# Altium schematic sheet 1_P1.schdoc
size 431 x 309 mm; Symbol: Sheet-Symbol_A4; Device: Sheet-Symbol_A4; @Page Name: P1; @Create Date: 2023-05-28; @Page Count: 1; @Page No: 1; @Project Name: esp32s3_tpkb; @Schematic Name: Schematic1; @Update Date: 2023-06-06; Company: 嘉立创EDA; Page Size: A4; Version: V1.0
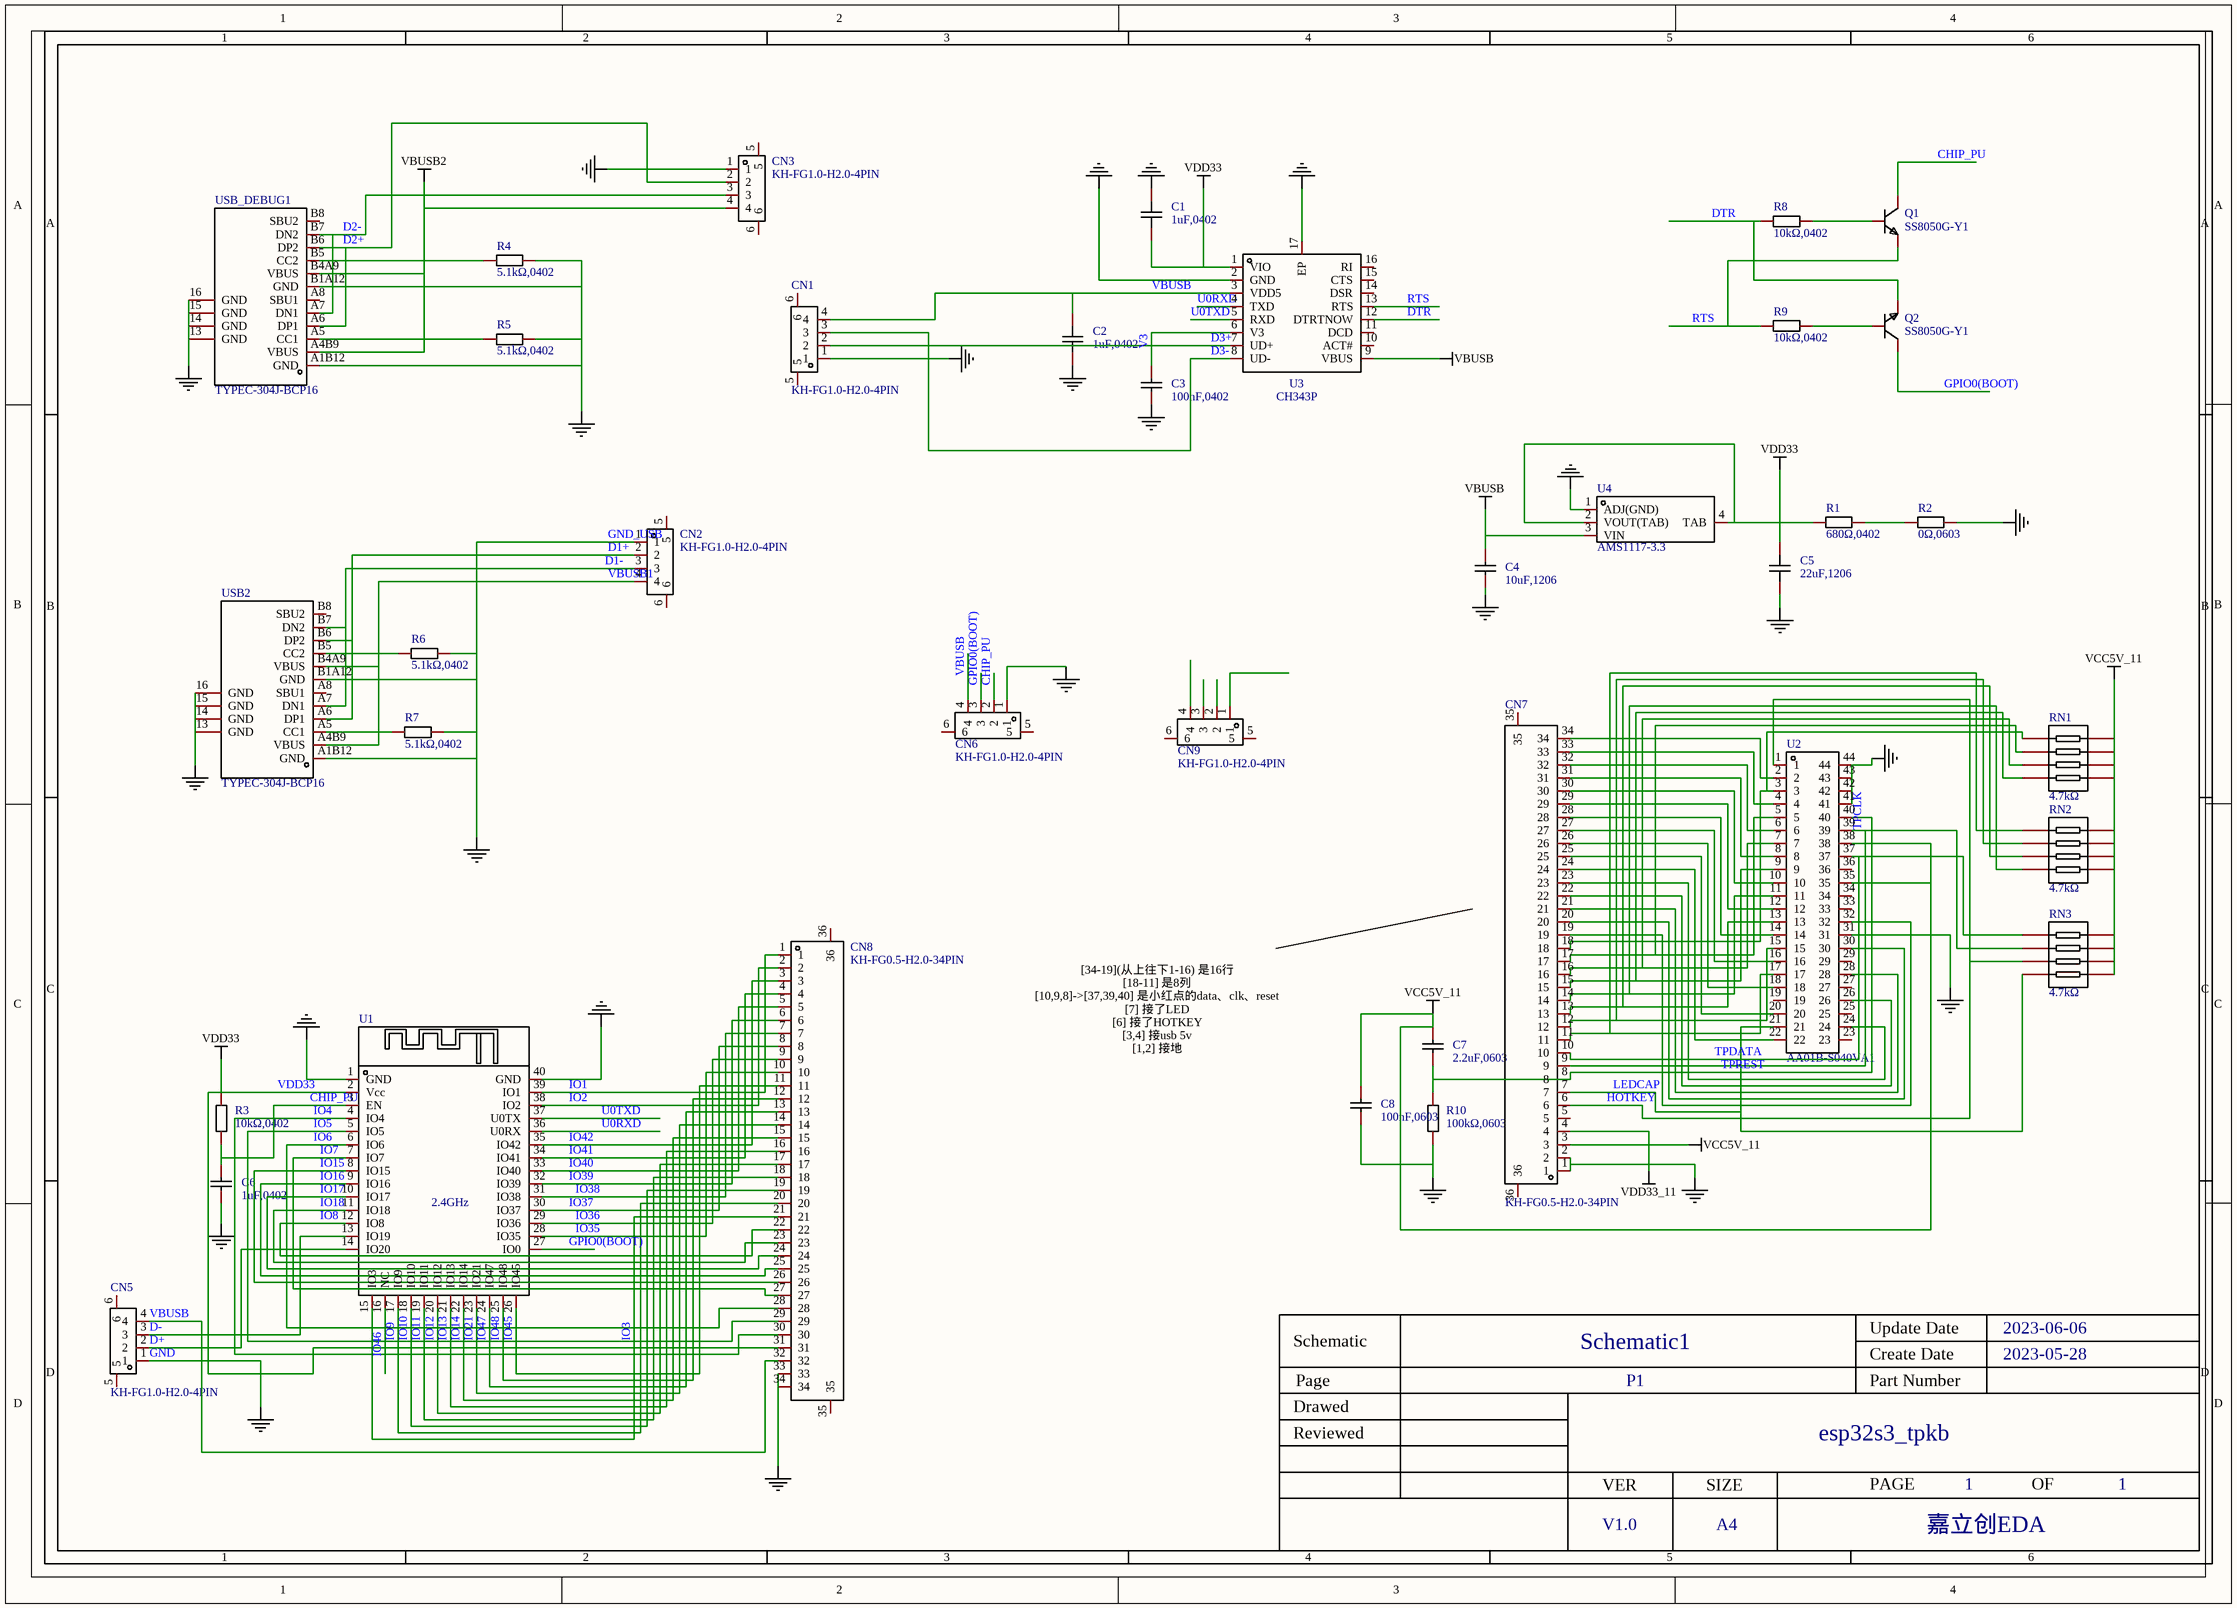
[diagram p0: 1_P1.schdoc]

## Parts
C1  1uF,0402  [C0402]
C2  1uF,0402  [C0402]
C3  100nF,0402  [C0402]
C4  10uF,1206  [C1206]
C5  22uF,1206  [C1206]
C6  1uF,0402  [C0402]
C7  2.2uF,0603  [C0603]
C8  100nF,0603  [C0603]
CN1  KH-FG1.0-H2.0-4PIN  [FPC-SMD_KH-FG1.0-H2.0-4PIN]
CN2  KH-FG1.0-H2.0-4PIN  [FPC-SMD_KH-FG1.0-H2.0-4PIN]
CN3  KH-FG1.0-H2.0-4PIN  [FPC-SMD_KH-FG1.0-H2.0-4PIN]
CN5  KH-FG1.0-H2.0-4PIN  [FPC-SMD_KH-FG1.0-H2.0-4PIN]
CN6  KH-FG1.0-H2.0-4PIN  [FPC-SMD_KH-FG1.0-H2.0-4PIN]
CN7  KH-FG0.5-H2.0-34PIN  [FPC-SMD_KH-FG0.5-H2.0-34PIN]
CN8  KH-FG0.5-H2.0-34PIN  [FPC-SMD_KH-FG0.5-H2.0-34PIN]
CN9  KH-FG1.0-H2.0-4PIN  [FPC-SMD_KH-FG1.0-H2.0-4PIN]
Q1  SS8050G-Y1  [SOT-23-3_L2.9-W1.3-P1.90-LS2.4-BR]
Q2  SS8050G-Y1  [SOT-23-3_L2.9-W1.3-P1.90-LS2.4-BR]
R1  680Ω,0402  [R0402]
R2  0Ω,0603  [R0603]
R3  10kΩ,0402  [R0402]
R4  5.1kΩ,0402  [R0402]
R5  5.1kΩ,0402  [R0402]
R6  5.1kΩ,0402  [R0402]
R7  5.1kΩ,0402  [R0402]
R8  10kΩ,0402  [R0402]
R9  10kΩ,0402  [R0402]
R10  100kΩ,0603  [R0603]
RN1  4.7kΩ  [RES-ARRAY-SMD_0603-8P-L3.2-W1.6-BL]
RN2  4.7kΩ  [RES-ARRAY-SMD_0603-8P-L3.2-W1.6-BL]
RN3  4.7kΩ  [RES-ARRAY-SMD_0603-8P-L3.2-W1.6-BL]
U1  2.4GHz  [WIFIM-SMD_40P-L25.5-W18.0-P1.27-TL]
U2  AA01B-S040VA1  [CONN-SMD_AA01B-S040VA1]
U3  CH343P  [TQFN-16_L3.0-W3.0-P0.50-BL-EP1.7]
U4  AMS1117-3.3  [SOT-223-4_L6.5-W3.5-P2.30-LS7.0-BR]
USB2  TYPEC-304J-BCP16  [USB-C-SMD_TYPEC-304J-BCP16]
USB_DEBUG1  TYPEC-304J-BCP16  [USB-C-SMD_TYPEC-304J-BCP16]

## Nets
GND: C1.2 C2.1 C3.1 C4.1 C5.1 C6.1 CN1.1 CN5.1 CN6.1 CN8.33 CN8.34 R2.2 U1.1(GND) U1.40(GND) U3.2(GND) U3.17(EP) U4.1(ADJ(GND))
GND_11: C8.1 CN7.1 CN7.2 R10.2 U2.31 U2.41 U2.42 U2.43 U2.44
GND_DEBUG: CN3.1 R4.2 R5.2 USB_DEBUG1.13(GND) USB_DEBUG1.14(GND) USB_DEBUG1.15(GND) USB_DEBUG1.16(GND) USB_DEBUG1.A1B12(GND) USB_DEBUG1.B1A12(GND)
GND_USB: CN2.1 R6.2 R7.2 USB2.13(GND) USB2.14(GND) USB2.15(GND) USB2.16(GND) USB2.A1B12(GND) USB2.B1A12(GND)
VBUSB: C2.2 C4.2 CN1.4 CN5.4 CN6.4 CN8.32 U3.3(VDD5) U3.9(VBUS) U4.3(VIN)
VBUSB2: CN3.4 USB_DEBUG1.A4B9(VBUS) USB_DEBUG1.B4A9(VBUS)
VCC5V_11: C7.1 C8.2 CN7.3 RN1.5 RN1.6 RN1.7 RN1.8 RN2.5 RN2.6 RN2.7 RN2.8 RN3.5 RN3.6 RN3.7 RN3.8 U2.35 U2.38
VDD33: C1.1 C5.2 CN8.31 R1.1 R3.2 U1.2(Vcc) U3.1(VIO) U4.2(VOUT(TAB)) U4.4(TAB)
VDD33_11: CN7.4
CHIP_PU: C6.2 CN6.2 Q1.3(C) R3.1 U1.3(EN)
D1+: CN2.2 USB2.A6(DP1) USB2.B6(DP2)
D1-: CN2.3 USB2.A7(DN1) USB2.B7(DN2)
D2+: CN3.2 USB_DEBUG1.A6(DP1) USB_DEBUG1.B6(DP2)
D2-: CN3.3 USB_DEBUG1.A7(DN1) USB_DEBUG1.B7(DN2)
D3+: CN1.2 U3.7(UD+)
D3-: CN1.3 U3.8(UD-)
D+: CN5.2 U1.14(IO20)
D-: CN5.3 U1.13(IO19)
DTR: Q2.2(E) R8.1 U3.12(DTRTNOW)
GPIO0(BOOT): CN6.3 Q2.3(C) U1.27(IO0)
HOTKEY: CN7.6 RN3.3 U2.1
IO1: CN8.1 U1.39(IO1)
IO2: CN8.2 U1.38(IO2)
IO4: CN8.30 U1.4(IO4)
IO6: CN8.28 U1.6(IO6)
IO7: CN8.27 U1.7(IO7)
IO8: CN8.22 U1.12(IO8)
IO10: CN8.11 CN8.12 CN8.13 CN8.14 CN8.15 CN8.16 CN8.17 CN8.18 CN8.19 CN8.20 CN8.21 CN8.29 U1.5(IO5) U1.15(IO3) U1.17(IO9) U1.18(IO10) U1.19(IO11) U1.20(IO12) U1.21(IO13) U1.22(IO14) U1.23(IO21) U1.24(IO47) U1.25(IO48) U1.26(IO45)  [also labelled IO11, IO12, IO13, IO14, IO21, IO3, IO45, IO47, IO48, IO5, IO9]
IO15: CN8.26 U1.8(IO15)
IO16: CN8.25 U1.9(IO16)
IO17: CN8.24 U1.10(IO17)
IO18: CN8.23 U1.11(IO18)
IO35: CN8.10 U1.28(IO35)
IO36: CN8.9 U1.29(IO36)
IO37: CN8.8 U1.30(IO37)
IO38: CN8.7 U1.31(IO38)
IO39: CN8.6 U1.32(IO39)
IO40: CN8.5 U1.33(IO40)
IO41: CN8.4 U1.34(IO41)
IO42: CN8.3 U1.35(IO42)
IO46: U1.16(NC)
LEDCAP: CN7.7 RN3.4 U2.21
RTS: Q1.2(E) R9.1 U3.13(RTS)
TPCLK: CN7.9 RN3.2 U2.39
TPDATA: CN7.10 RN3.1 U2.37
TPREST: C7.2 CN7.8 R10.1 U2.40
U0RXD: U1.36(U0RX) U3.4(TXD)
U0TXD: U1.37(U0TX) U3.5(RXD)
V3: C3.2 U3.6(V3)
VBUSB1: CN2.4 USB2.A4B9(VBUS) USB2.B4A9(VBUS)
NetCN7_11: CN7.11 RN2.1 U2.17
NetCN7_12: CN7.12 RN2.2 U2.15
NetCN7_13: CN7.13 RN2.3 U2.13
NetCN7_14: CN7.14 RN2.4 U2.11
NetCN7_15: CN7.15 RN1.4 U2.9
NetCN7_16: CN7.16 RN1.3 U2.7
NetCN7_17: CN7.17 RN1.2 U2.5
NetCN7_18: CN7.18 RN1.1 U2.3
NetCN7_19: CN7.19 U2.32
NetCN7_20: CN7.20 U2.30
NetCN7_21: CN7.21 U2.28
NetCN7_22: CN7.22 U2.26
NetCN7_23: CN7.23 U2.24
NetCN7_24: CN7.24 U2.22
NetCN7_25: CN7.25 U2.20
NetCN7_26: CN7.26 U2.18
NetCN7_27: CN7.27 U2.16
NetCN7_28: CN7.28 U2.14
NetCN7_29: CN7.29 U2.12
NetCN7_30: CN7.30 U2.10
NetCN7_31: CN7.31 U2.8
NetCN7_32: CN7.32 U2.6
NetCN7_33: CN7.33 U2.4
NetCN7_34: CN7.34 U2.2
NetQ1_1: Q1.1(B) R8.2
NetQ2_1: Q2.1(B) R9.2
NetR1_2: R1.2 R2.1
NetR4_1: R4.1 USB_DEBUG1.B5(CC2)
NetR5_1: R5.1 USB_DEBUG1.A5(CC1)
NetR6_1: R6.1 USB2.B5(CC2)
NetR7_1: R7.1 USB2.A5(CC1)

Not connected (* = marked no-connect by the designer): CN1 5 6; CN2 5 6; CN3 5 6; CN5 5 6; CN6 5 6; CN7 5 35 36; CN8 35 36; CN9 1 2 3 4 5 6; U2 19 23 25 27 29 33 34 36; U3 10(ACT#) 11(DCD) 14(DSR) 15(CTS) 16(RI); USB2 A8(SBU1) B8(SBU2); USB_DEBUG1 A8(SBU1) B8(SBU2)

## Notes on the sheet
- [34-19](从上往下1-16) 是16行
  [18-11] 是8列
  [10,9,8]->[37,39,40] 是小红点的data、clk、reset
  [7] 接了LED
  [6] 接了HOTKEY
  [3,4] 接usb 5v
  [1,2] 接地

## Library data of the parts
C1 C2 = CL05A105KA5NQNC: 容值:1uF;精度:±10%;额定电压:25V;材质(温度系数):X5R;; Manufacturer: SAMSUNG(三星); Add into BOM: yes; Tolerance: ±10%; Voltage Rated: 25V; Temperature Coefficient: X5R
C3 = CL05B104KO5NNNC: 容值:100nF;精度:±10%;额定电压:16V;材质(温度系数):X7R;; Manufacturer: SAMSUNG(三星); Add into BOM: yes; Tolerance: ±10%; Voltage Rated: 16V; Temperature Coefficient: X7R
C4 = CL31A106KBHNNNE: 容值:10uF;精度:±10%;额定电压:50V;材质(温度系数):X5R;; Manufacturer: SAMSUNG(三星); Add into BOM: yes; Tolerance: ±10%; Voltage Rated: 50V; Temperature Coefficient: X5R
C5 = C3216X5R1V226MTJ00E: 容值:22uF;精度:±20%;额定电压:35V;材质(温度系数):X5R;; Manufacturer: TDK; Add into BOM: yes; Tolerance: ±20%; Voltage Rated: 35V; Temperature Coefficient: X5R
C6 = CL05A105KP5NNNC: 容值:1uF;精度:±10%;额定电压:10V;材质(温度系数):X5R;; Manufacturer: SAMSUNG(三星); Add into BOM: yes; Tolerance: ±10%; Voltage Rated: 10V; Temperature Coefficient: X5R
C7 = CL10A225KO8NNNC: 容值:2.2uF;精度:±10%;额定电压:16V;材质(温度系数):X5R;; Manufacturer: SAMSUNG(三星); Add into BOM: yes; Tolerance: ±10%; Voltage Rated: 16V; Temperature Coefficient: X5R
C8 = 0603B104K500NT: 容值:100nF;精度:±10%;额定电压:50V;材质(温度系数):X7R;; Manufacturer: FH(风华); Add into BOM: yes; Tolerance: ±10%; Voltage Rated: 50V; Temperature Coefficient: X7R
CN1-CN3 CN5 CN6 CN9 = KH-FG1.0-H2.0-4PIN: 间距:1mm;触点数量:4;锁定特性:翻盖式;安装类型:卧贴;触点类型:下接;工作温度范围:-25℃~+85℃;; Manufacturer: kinghelm(金航标); Add into BOM: yes; Pitch: 1mm; Number of Contacts: 4; Locking Feature: 翻盖式; FFC, FCB Thickness: 0.3mm
CN7 CN8 = KH-FG0.5-H2.0-34PIN: 间距:0.5mm;触点数量:34;锁定特性:翻盖式;安装类型:卧贴;触点类型:下接;工作温度范围:-25℃~+85℃;; Manufacturer: kinghelm(金航标); Add into BOM: yes; Pitch: 0.5mm; Number of Contacts: 34; Locking Feature: 翻盖式; FFC, FCB Thickness: 0.3mm
Q1 Q2 = SS8050G-Y1: 晶体管类型:NPN;集射极击穿电压(Vceo):25V;集电极电流(Ic):1.5A;功率(Pd):300mW;集电极截止电流(Icbo):100nA;集电极-发射极饱和电压(VCE(sat)@Ic,Ib):280mV@800mA,80mA;特征频率(fT):190MHz;工作温度:-55℃~+150℃@(Tj);; Manufacturer: 银河微电子; Add into BOM: yes; Transistor Type: NPN; Collector-Emitter Breakdown Voltage (Vceo): 25V; Collector Current (Ic): 1.5A; Power Dissipation (Pd): 300mW; Collector Cut-Off Current (Icbo): 100nA; Transition Frequency (fT): 190MHz
R1 = 0402WGF6800TCE: 电阻类型:厚膜电阻;阻值:680Ω;精度:±1%;功率:62.5mW;; Manufacturer: UNI-ROYAL(厚声); Add into BOM: yes; Tolerance: ±1%; Power(Watts): 62.5mW; Temperature Coefficient: ±100ppm/℃; Overload Voltage (Max): 50V
R2 = 0603WAF0000T5E: 电阻类型:厚膜电阻;阻值:0Ω;精度:±1%;功率:100mW;; Manufacturer: UNI-ROYAL(厚声); Add into BOM: yes; Tolerance: ±1%; Power(Watts): 100mW; Overload Voltage (Max): 75V
R3 R8 R9 = 0402WGF1002TCE: 电阻类型:厚膜电阻;阻值:10kΩ;精度:±1%;功率:62.5mW;; Manufacturer: UNI-ROYAL(厚声); Add into BOM: yes; Tolerance: ±1%; Power(Watts): 62.5mW; Temperature Coefficient: ±100ppm/℃; Overload Voltage (Max): 50V
R4-R7 = 0402WGF5101TCE: 电阻类型:厚膜电阻;阻值:5.1kΩ;精度:±1%;功率:62.5mW;; Manufacturer: UNI-ROYAL(厚声); Add into BOM: yes; Tolerance: ±1%; Power(Watts): 62.5mW; Temperature Coefficient: ±100ppm/℃; Overload Voltage (Max): 50V
R10 = 0603WAF1003T5E: 电阻类型:厚膜电阻;阻值:100kΩ;精度:±1%;功率:100mW;; Manufacturer: UNI-ROYAL(厚声); Add into BOM: yes; Tolerance: ±1%; Power(Watts): 100mW; Temperature Coefficient: ±100ppm/℃; Overload Voltage (Max): 75V
RN1-RN3 = 4D03WGJ0472T5E: 阻值:4.7kΩ;精度:±5%;单个元件功率:62.5mW;电阻器数:4;; Manufacturer: UNI-ROYAL(厚声); Add into BOM: yes; Tolerance: ±5%; Power(Watts): 62.5mW; Number of Resistors: 4; Temperature Coefficient: ±200ppm/℃
U1 = ESP-S3-32S: 频率:2.4GHz;发射功率:20dBm;核心处理器:LX7;天线形式:板载 PCB 天线/IPEX 座;接收灵敏度:-97dBm;; Manufacturer: Ai-Thinker(安信可); Add into BOM: yes; Output Power: 20dBm; Core Processor: LX7; Support Interface: I2C；GPIO；UART；PWM；SPI；ADC；I2S; Wireless Standard: 802.11b/g/n; Operating Voltage: 3.3V; Receive  Current: 100mA; Send  Current: 350mA; Sensitivity: -97dBm
U2 = AA01B-S040VA1: Add into BOM: yes
U3 = CH343P: 类型:-;协议类别:-;驱动器/接收器数:-;数据速率:-;; Manufacturer: WCH(南京沁恒); Add into BOM: yes; Pin Type: IN
U4 = AMS1117-3.3_C347222: 输出类型:固定;输出极性:正;最大输入电压:18V;输出电压:3.3V;输出电流:1A;电源纹波抑制比(PSRR):60dB@(120Hz);; Manufacturer: UMW(广东友台半导体); Add into BOM: yes; Output Type: 固定; Output Polarity: 正; Number of Outputs: 1; Maximum Input Voltage: 18V; Output Voltage: 3.3V; Dropout Voltage: 1.3V@(1A); Output Current: 1A
USB2 USB_DEBUG1 = TYPEC-304J-BCP16: 连接器类型:Type-C;标准:USB 3.1;公母:母座;触点数量:16;端口数量:1;安装方式:卧贴;额定电流 - 电源:5A;工作温度范围:-40℃~+85℃;焊接温度(最大值):260℃;; Manufacturer: XUNPU(讯普); Add into BOM: yes; Connector Type: Type-C; Gender: 母座; Number of Contacts: 16; Number of Ports: 1; Current Rating - Power (Max): 5A; Welding Temperature (Max): 260℃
